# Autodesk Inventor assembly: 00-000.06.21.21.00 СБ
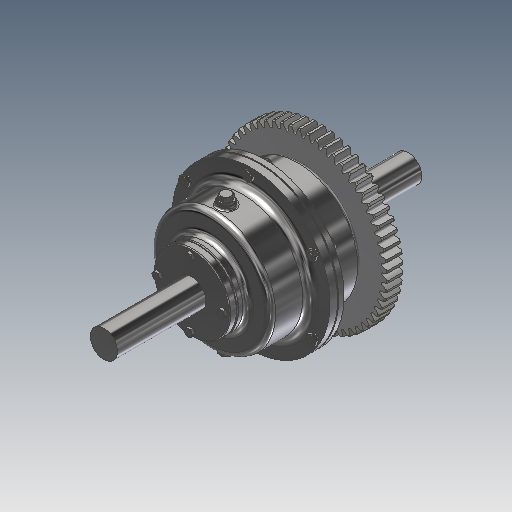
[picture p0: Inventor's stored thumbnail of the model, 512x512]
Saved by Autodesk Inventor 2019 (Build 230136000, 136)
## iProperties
Created: 2019-01
Part Number: 00-000.06.21.21.00 СБ
Document SubType Name: Assembly
Designer: m.vorobev
Author: m.vorobev
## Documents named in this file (31)
- C:\Users\m.vorobev.TRINITY\Documents\Inventor\00-000.06.21.21.00\Animation-01.iam
- C:\Users\m.vorobev.TRINITY\Documents\Inventor\00-000.06.21.21.00\00-000.06.21.21.10.ipt
- C:\Users\m.vorobev.TRINITY\Documents\Inventor\00-000.06.21.21.00\00-000.06.21.21.01.ipt
- C:\Users\m.vorobev.TRINITY\Documents\Inventor\00-000.06.21.21.00\00-000.06.21.21.02.ipt
- C:\Users\m.vorobev.TRINITY\Documents\Inventor\00-000.06.21.21.00\Content Center Files\en-US\Bolt GOST 7798-78\Bolt  M10-6g×35(S16) GOST 7798-70.ipt
- C:\Users\m.vorobev.TRINITY\Documents\Inventor\00-000.06.21.21.00\Content Center Files\en-US\GOST 6402-70\Washer  10 L GOST 6402-70.ipt
- C:\Users\m.vorobev.TRINITY\Documents\Inventor\00-000.06.21.21.00\Content Center Files\en-US\GOST 5916-70\Nut M10-6H GOST 5916-70.ipt
- C:\Users\m.vorobev.TRINITY\Documents\Inventor\00-000.06.21.21.00\00-000.06.21.21.15.ipt
- C:\Users\m.vorobev.TRINITY\Documents\Inventor\00-000.06.21.21.00\00-000.06.21.21.05.ipt
- C:\Users\m.vorobev.TRINITY\Documents\Inventor\00-000.06.21.21.00\Content Center Files\Key 2-36x20x100 GOST 23360-78.ipt
- C:\Users\m.vorobev.TRINITY\Documents\Inventor\00-000.06.21.21.00\Content Center Files\en-US\Stud GOST 22034-76\Stud M10-6g×45 GOST 22034-76.ipt
- C:\Users\m.vorobev.TRINITY\Documents\Inventor\00-000.06.21.21.00\00-000.06.21.21.07.ipt
- C:\Users\m.vorobev.TRINITY\Documents\Inventor\00-000.06.21.21.00\00-000.06.21.21.11,12,13\00-000.06.21.21.12.ipt
- C:\Users\m.vorobev.TRINITY\Documents\Inventor\00-000.06.21.21.00\00-000.06.21.21.11,12,13.ipt
- C:\Users\m.vorobev.TRINITY\Documents\Inventor\00-000.06.21.21.00\00-000.06.21.21.03.ipt
- C:\Users\m.vorobev.TRINITY\Documents\Inventor\00-000.06.21.21.00\00-000.06.21.21.04.ipt
- C:\Users\m.vorobev.TRINITY\Documents\Inventor\00-000.06.21.21.00\Content Center Files\Key 2-12x8x28 GOST 23360-78.ipt
- C:\Users\m.vorobev.TRINITY\Documents\Inventor\00-000.06.21.21.00\Content Center Files\en-US\Nut GOST 12460-67\Nut 7003-0141 GOST 12460-67.ipt
- C:\Users\m.vorobev.TRINITY\Documents\Inventor\00-000.06.21.21.00\00-000.06.21.21.11,12,13\00-000.06.21.21.11.ipt
- C:\Users\m.vorobev.TRINITY\Documents\Inventor\00-000.06.21.21.00\Content Center Files\en-US\GOST 8338-75\Bearing 309 GOST 8338-75.ipt
- C:\Users\m.vorobev.TRINITY\Documents\Inventor\00-000.06.21.21.00\00-000.06.21.21.11,12,13\00-000.06.21.21.13.ipt
- C:\Users\m.vorobev.TRINITY\Documents\Inventor\00-000.06.21.21.00\00-000.06.21.21.08,09\00-000.06.21.21.08.ipt
- C:\Users\m.vorobev.TRINITY\Documents\Inventor\00-000.06.21.21.00\00-000.06.21.21.08,09.ipt
- C:\Users\m.vorobev.TRINITY\Documents\Inventor\00-000.06.21.21.00\00-000.06.21.21.08,09\00-000.06.21.21.09.ipt
- C:\Users\m.vorobev.TRINITY\Documents\Inventor\00-000.06.21.21.00\00-000.06.21.21.29.ipt
- C:\Users\m.vorobev.TRINITY\Documents\Inventor\00-000.06.21.21.00\Content Center Files\en-US\GOST 6402-70\Washer  8 L GOST 6402-70.ipt
- C:\Users\m.vorobev.TRINITY\Documents\Inventor\00-000.06.21.21.00\Content Center Files\en-US\Bolt GOST 7798-78\Bolt  M8-6g×35(S13) GOST 7798-70.ipt
- C:\Users\m.vorobev.TRINITY\Documents\Inventor\00-000.06.21.21.00\00-000.06.21.21.06.ipt
- C:\Users\m.vorobev.TRINITY\Documents\Inventor\00-000.06.21.21.00\00-000.06.21.21.17.ipt
- C:\Users\m.vorobev.TRINITY\Documents\Inventor\00-000.06.21.21.00\00-000.06.21.21.16.ipt
- C:\Users\m.vorobev.TRINITY\Documents\Inventor\00-000.06.21.21.00\00-000.06.21.21.14.ipt
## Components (106 placed, 28 different names)
1. 00-000.06.21.21.05:1 — Angle:1, Insert:21, Flush:1, Angle:4, Mate:25
2. 00-000.06.21.21.10:1 — Mate:4, Mate:5, Mate:6, Mate:7, Mate:8, Mate:16, Mate:23
3. 00-000.06.21.21.01:1 — Mate:19, Insert:70, Mate:21, Insert:90, Mate:22, Insert:93, Insert:95, Insert:97, Mate:24, Mate:26
4. 00-000.06.21.21.02:1 — Insert:19, Mate:1, Mate:2, Mate:3, Insert:20, Insert:21, Mate:18, Insert:53, Insert:71, Mate:20, Mate:23, Insert:95
5. 00-000.06.21.21.15:1 — Insert:19
6. Key 2-36x20x100 GOST 23360-78:1 — Mate:1, Mate:2, Mate:3, Angle:1
7. 00-000.06.21.21.07:1 — Mate:14, Insert:44, Mate:15, Mate:17, Insert:45, Insert:46, Insert:47, Insert:48, Mate:24
8. 00-000.06.21.21.12:1 — Insert:38, Insert:44
9. 00-000.06.21.21.12:2 — Insert:39, Insert:47
10. 00-000.06.21.21.12:3 — Insert:41, Insert:46
11. 00-000.06.21.21.12:4 — Insert:40, Insert:45
12. 00-000.06.21.21.03:1 — Insert:38, Rotation:3
13. 00-000.06.21.21.03:2 — Insert:39, Rotation:2
14. 00-000.06.21.21.03:3 — Insert:40, Rotation:4
15. 00-000.06.21.21.03:4 — Insert:41, Rotation:2, Rotation:3, Rotation:4, Rotation:5
16. 00-000.06.21.21.04:1 — Mate:7, Angle:2, Mate:8, Insert:42, Mate:15, Insert:49, Rotation:1, Rotation:5, Rotating
17. Key 2-12x8x28 GOST 23360-78:1 — Mate:4, Mate:5, Mate:6, Angle:2
18. 00-000.06.21.21.10:2 — Mate:16, Mate:22
19. 00-000.06.21.21.04:2 — Mate:17, Insert:50, Rotation:1
20. Key 2-12x8x28 GOST 23360-78:2
21. 00-000.06.21.21.11:5 — Insert:48
22. 00-000.06.21.21.13:6 — Insert:49
23. 00-000.06.21.21.13:7 — Insert:50
24. 00-000.06.21.21.08:1 — Insert:51, Mate:18, Insert:53, Insert:80
25. 00-000.06.21.21.09:2 — Insert:52, Insert:63, Insert:67, Insert:68, Insert:69, Mate:19, Insert:70, Insert:89, Insert:91
26. 00-000.06.21.21.29:1 — Insert:51
27. 00-000.06.21.21.29:2 — Insert:52
28. 00-000.06.21.21.06:1 — Insert:71, Mate:20, Insert:76, Insert:77, Insert:78, Insert:79
29. 00-000.06.21.21.06:2 — Mate:21, Insert:90
30. 00-000.06.21.21.17:1 — Insert:93, Insert:94
31. 00-000.06.21.21.16:1 — Insert:91
32. 00-000.06.21.21.14:1 — Insert:94
33. 00-000.06.21.21.17:2 — Insert:97
34. 00-000.06.21.21.14:2
35. Bolt GOST 7798-70 M10-6g×35(S16):1
36. Bolt GOST 7798-70 M10-6g×35(S16):2
37. Bolt GOST 7798-70 M10-6g×35(S16):3
38. Bolt GOST 7798-70 M10-6g×35(S16):4
39. Bolt GOST 7798-70 M10-6g×35(S16):5
40. Bolt GOST 7798-70 M10-6g×35(S16):6
41. Washer GOST 6402-70 10 L:1
42. Washer GOST 6402-70 10 L:2
43. Washer GOST 6402-70 10 L:3
44. Washer GOST 6402-70 10 L:4
45. Washer GOST 6402-70 10 L:5
46. Washer GOST 6402-70 10 L:6
47. Nut GOST 5916-70 M10:1
48. Nut GOST 5916-70 M10:2
49. Nut GOST 5916-70 M10:3
50. Nut GOST 5916-70 M10:4
51. Nut GOST 5916-70 M10:5
52. Nut GOST 5916-70 M10:6
53. Washer GOST 6402-70 10 L:7 — Insert:28
54. Washer GOST 6402-70 10 L:8 — Insert:33
55. Washer GOST 6402-70 10 L:9 — Insert:32
56. Washer GOST 6402-70 10 L:10 — Insert:31
57. Washer GOST 6402-70 10 L:11 — Insert:30
58. Washer GOST 6402-70 10 L:12 — Insert:29
59. Nut GOST 5916-70 M10:7 — Insert:28
60. Nut GOST 5916-70 M10:8 — Insert:33
61. Nut GOST 5916-70 M10:9 — Insert:29
62. Nut GOST 5916-70 M10:10 — Insert:30
63. Nut GOST 5916-70 M10:11 — Insert:31
64. Nut GOST 5916-70 M10:12 — Insert:32
65. Nut GOST 12460-67 7003-0141:1 — Insert:42, Mate:14
66. Nut GOST 12460-67 7003-0141:3
67. Bearing GOST 8338-75 309:1 — Insert:89
68. Washer GOST 6402-70 8 L:1
69. Washer GOST 6402-70 8 L:2 — Insert:59
70. Washer GOST 6402-70 8 L:3 — Insert:61
71. Washer GOST 6402-70 8 L:4 — Insert:60
72. Bolt GOST 7798-70 M8-6g×35(S13):1
73. Bolt GOST 7798-70 M8-6g×35(S13):2 — Insert:59
74. Bolt GOST 7798-70 M8-6g×35(S13):3 — Insert:61
75. Bolt GOST 7798-70 M8-6g×35(S13):4 — Insert:60
76. Washer GOST 6402-70 8 L:5 — Insert:63
77. Bolt GOST 7798-70 M8-6g×35(S13):5
78. Washer GOST 6402-70 8 L:6 — Insert:68
79. Bolt GOST 7798-70 M8-6g×35(S13):6
80. Washer GOST 6402-70 8 L:7 — Insert:69
81. Bolt GOST 7798-70 M8-6g×35(S13):7
82. Washer GOST 6402-70 8 L:8 — Insert:67
83. Bolt GOST 7798-70 M8-6g×35(S13):8
84. Washer GOST 6402-70 8 L:9 — Insert:78
85. Bolt GOST 7798-70 M8-6g×35(S13):9
86. Washer GOST 6402-70 8 L:10 — Insert:76
87. Bolt GOST 7798-70 M8-6g×35(S13):10
88. Washer GOST 6402-70 8 L:11 — Insert:79
89. Bolt GOST 7798-70 M8-6g×35(S13):11
90. Washer GOST 6402-70 8 L:12 — Insert:77
91. Bolt GOST 7798-70 M8-6g×35(S13):12
92. Bearing GOST 8338-75 309:2 — Insert:80
93. Washer GOST 6402-70 8 L:13
94. Bolt GOST 7798-70 M8-6g×35(S13):13
95. Washer GOST 6402-70 8 L:14
96. Bolt GOST 7798-70 M8-6g×35(S13):14
97. Washer GOST 6402-70 8 L:15
98. Bolt GOST 7798-70 M8-6g×35(S13):15
99. Washer GOST 6402-70 8 L:16
100. Bolt GOST 7798-70 M8-6g×35(S13):16
101. Stud GOST 22034-76 M10-6g×45:1 — Insert:20
102. Stud GOST 22034-76 M10-6g×45:2
103. Stud GOST 22034-76 M10-6g×45:3
104. Stud GOST 22034-76 M10-6g×45:4
105. Stud GOST 22034-76 M10-6g×45:5
106. Stud GOST 22034-76 M10-6g×45:6
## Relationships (76: Insert 45, Mate 21, RelateRotation 5, Angle 4, Flush 1)
- Insert:19: 00-000.06.21.21.02:1 ↔ 00-000.06.21.21.15:1
- Mate:1: 00-000.06.21.21.02:1 ↔ Key 2-36x20x100 GOST 23360-78:1
- Mate:2: 00-000.06.21.21.02:1 ↔ Key 2-36x20x100 GOST 23360-78:1
- Mate:3: 00-000.06.21.21.02:1 ↔ Key 2-36x20x100 GOST 23360-78:1
- Insert:20: 00-000.06.21.21.02:1 ↔ Stud GOST 22034-76 M10-6g×45:1
- Angle:1: 00-000.06.21.21.05:1 ↔ Key 2-36x20x100 GOST 23360-78:1
- Insert:21: 00-000.06.21.21.05:1 ↔ 00-000.06.21.21.02:1
- Insert:28: Washer GOST 6402-70 10 L:7 ↔ Nut GOST 5916-70 M10:7
- Insert:29: Washer GOST 6402-70 10 L:12 ↔ Nut GOST 5916-70 M10:9
- Insert:30: Washer GOST 6402-70 10 L:11 ↔ Nut GOST 5916-70 M10:10
- Insert:31: Washer GOST 6402-70 10 L:10 ↔ Nut GOST 5916-70 M10:11
- Insert:32: Washer GOST 6402-70 10 L:9 ↔ Nut GOST 5916-70 M10:12
- Insert:33: Washer GOST 6402-70 10 L:8 ↔ Nut GOST 5916-70 M10:8
- Insert:38: 00-000.06.21.21.12:1 ↔ 00-000.06.21.21.03:1
- Insert:39: 00-000.06.21.21.12:2 ↔ 00-000.06.21.21.03:2
- Insert:40: 00-000.06.21.21.12:4 ↔ 00-000.06.21.21.03:3
- Insert:41: 00-000.06.21.21.12:3 ↔ 00-000.06.21.21.03:4
- Mate:4: 00-000.06.21.21.10:1 ↔ Key 2-12x8x28 GOST 23360-78:1
- Mate:5: 00-000.06.21.21.10:1 ↔ Key 2-12x8x28 GOST 23360-78:1
- Mate:6: 00-000.06.21.21.10:1 ↔ Key 2-12x8x28 GOST 23360-78:1
- Mate:7: 00-000.06.21.21.10:1 ↔ 00-000.06.21.21.04:1
- Angle:2: 00-000.06.21.21.04:1 ↔ Key 2-12x8x28 GOST 23360-78:1
- Mate:8: 00-000.06.21.21.10:1 ↔ 00-000.06.21.21.04:1
- Insert:42: 00-000.06.21.21.04:1 ↔ Nut GOST 12460-67 7003-0141:1
- Mate:14: 00-000.06.21.21.07:1 ↔ Nut GOST 12460-67 7003-0141:1
- Insert:44: 00-000.06.21.21.07:1 ↔ 00-000.06.21.21.12:1
- Mate:15: 00-000.06.21.21.07:1 ↔ 00-000.06.21.21.04:1
- Mate:16: 00-000.06.21.21.10:1 ↔ 00-000.06.21.21.10:2
- Mate:17: 00-000.06.21.21.07:1 ↔ 00-000.06.21.21.04:2
- Insert:45: 00-000.06.21.21.07:1 ↔ 00-000.06.21.21.12:4
- Insert:46: 00-000.06.21.21.07:1 ↔ 00-000.06.21.21.12:3
- Insert:47: 00-000.06.21.21.07:1 ↔ 00-000.06.21.21.12:2
- Insert:48: 00-000.06.21.21.07:1 ↔ 00-000.06.21.21.11:5
- Insert:49: 00-000.06.21.21.04:1 ↔ 00-000.06.21.21.13:6
- Insert:50: 00-000.06.21.21.04:2 ↔ 00-000.06.21.21.13:7
- Insert:51: 00-000.06.21.21.08:1 ↔ 00-000.06.21.21.29:1
- Insert:52: 00-000.06.21.21.09:2 ↔ 00-000.06.21.21.29:2
- Mate:18: 00-000.06.21.21.02:1 ↔ 00-000.06.21.21.08:1
- Insert:53: 00-000.06.21.21.02:1 ↔ 00-000.06.21.21.08:1
- Insert:59: Washer GOST 6402-70 8 L:2 ↔ Bolt GOST 7798-70 M8-6g×35(S13):2
- Insert:60: Washer GOST 6402-70 8 L:4 ↔ Bolt GOST 7798-70 M8-6g×35(S13):4
- Insert:61: Washer GOST 6402-70 8 L:3 ↔ Bolt GOST 7798-70 M8-6g×35(S13):3
- Insert:63: 00-000.06.21.21.09:2 ↔ Washer GOST 6402-70 8 L:5
- Insert:67: 00-000.06.21.21.09:2 ↔ Washer GOST 6402-70 8 L:8
- Insert:68: 00-000.06.21.21.09:2 ↔ Washer GOST 6402-70 8 L:6
- Insert:69: 00-000.06.21.21.09:2 ↔ Washer GOST 6402-70 8 L:7
- Mate:19: 00-000.06.21.21.01:1 ↔ 00-000.06.21.21.09:2
- Insert:70: 00-000.06.21.21.01:1 ↔ 00-000.06.21.21.09:2
- Insert:71: 00-000.06.21.21.02:1 ↔ 00-000.06.21.21.06:1
- Mate:20: 00-000.06.21.21.02:1 ↔ 00-000.06.21.21.06:1
- Insert:76: 00-000.06.21.21.06:1 ↔ Washer GOST 6402-70 8 L:10
- Insert:77: 00-000.06.21.21.06:1 ↔ Washer GOST 6402-70 8 L:12
- Insert:78: 00-000.06.21.21.06:1 ↔ Washer GOST 6402-70 8 L:9
- Insert:79: 00-000.06.21.21.06:1 ↔ Washer GOST 6402-70 8 L:11
- Insert:80: 00-000.06.21.21.08:1 ↔ Bearing GOST 8338-75 309:2
- Mate:21: 00-000.06.21.21.01:1 ↔ 00-000.06.21.21.06:2
- Insert:89: 00-000.06.21.21.09:2 ↔ Bearing GOST 8338-75 309:1
- Insert:90: 00-000.06.21.21.01:1 ↔ 00-000.06.21.21.06:2
- Mate:22: 00-000.06.21.21.01:1 ↔ 00-000.06.21.21.10:2
- Mate:23: 00-000.06.21.21.10:1 ↔ 00-000.06.21.21.02:1
- Insert:91: 00-000.06.21.21.09:2 ↔ 00-000.06.21.21.16:1
- Insert:93: 00-000.06.21.21.01:1 ↔ 00-000.06.21.21.17:1
- Insert:94: 00-000.06.21.21.17:1 ↔ 00-000.06.21.21.14:1
- Insert:95: 00-000.06.21.21.01:1 ↔ 00-000.06.21.21.02:1
- Flush:1: 00-000.06.21.21.05:1
- Angle:4: 00-000.06.21.21.05:1
- Insert:97: 00-000.06.21.21.01:1 ↔ 00-000.06.21.21.17:2
- Mate:24: 00-000.06.21.21.01:1 ↔ 00-000.06.21.21.07:1
- Mate:25: 00-000.06.21.21.05:1
- Rotation:1 [RelateRotation]: 00-000.06.21.21.04:1 ↔ 00-000.06.21.21.04:2
- Rotation:2 [RelateRotation]: 00-000.06.21.21.03:2 ↔ 00-000.06.21.21.03:4
- Rotation:3 [RelateRotation]: 00-000.06.21.21.03:1 ↔ 00-000.06.21.21.03:4
- Rotation:4 [RelateRotation]: 00-000.06.21.21.03:3 ↔ 00-000.06.21.21.03:4
- Rotation:5 [RelateRotation]: 00-000.06.21.21.03:4 ↔ 00-000.06.21.21.04:1
- Rotating [Angle]: 00-000.06.21.21.04:1
- Mate:26: 00-000.06.21.21.01:1
## Named parameters: d52_d49 = 0, d54_d51 = 0, d55_d45 = 0, d56_d46 = 0, d57_d47 = 0, d58_d48 = 0, d88_d84 = 0, d90_d88_d84 = 0, d91_d88_d84 = 0, d92_d88_d84 = 0, d100_d84 = 0, d101_d100_d84 = 0, d102_d100_d84 = 0, d103_d100_d84 = 0, d109_d100_d84 = 0, d110_d101_d100_d84 = 0, d111_d102_d100_d84 = 0, d112_d103_d100_d84 = 0, d113_d104 = 0, d114_d105 = 0, d115_d106 = 0, d116_d107 = 0, d139_d125 = 0
